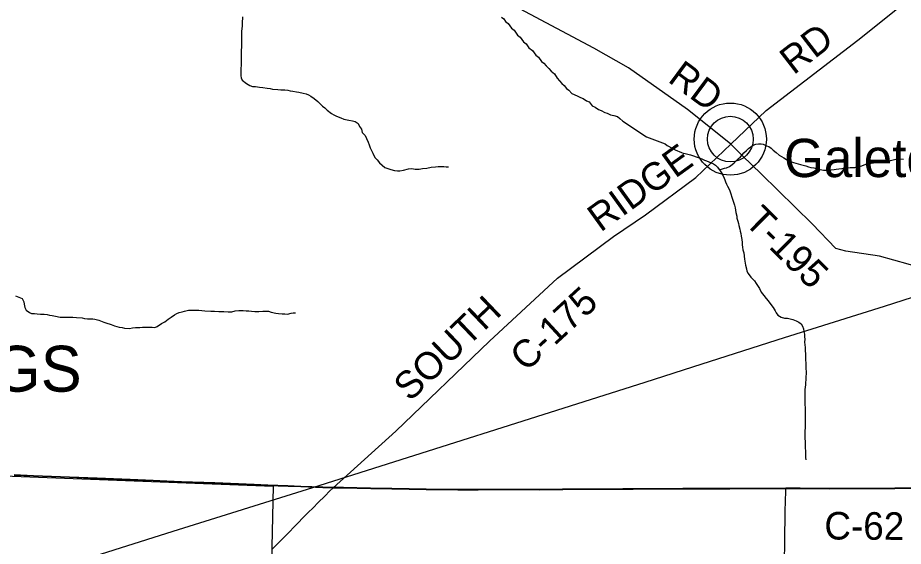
# Model space of a CAD drawing. Extents: x -8.5 to 18.7, y -20.3 to 7.
# Drawn here: x 4.267 to 7.92, y -11.043 to -8.863 of the extents above; entities that cross this region are included whole.
import ezdxf

# ---------------------------------------------------------------- set-up
doc = ezdxf.new("R2010")
doc.units = 0
for name, color, linetype in [('GM_X_Corporation', 7, 'Continuous'), ('GM_X_Corporation_Text', 7, 'Continuous'), ('GM_X_County_Road', 7, 'Continuous'), ('GM_X_County_Road_Text', 7, 'Continuous'), ('GM_X_Minor_River', 7, 'Continuous'), ('GM_X_Rail_Line', 7, 'Continuous'), ('GM_X_Section', 7, 'Continuous'), ('GM_X_Township', 7, 'Continuous'), ('GM_X_Township_Road', 7, 'Continuous'), ('GM_X_Township_Road_Text', 7, 'Continuous'), ('GM_X_Unincorporated', 7, 'Continuous'), ('GM_X_Unincorporated_Location', 7, 'Continuous'), ('GM_X_Unincorporated_Text', 7, 'Continuous'), ('SH_Cut_Line', 7, 'Continuous')]:
    doc.layers.add(name, color=color, linetype=linetype)

msp = doc.modelspace()

# ---------------------------------------------------------------- linework, layer by layer
at = {"layer": 'GM_X_Corporation'}
msp.add_lwpolyline([(8.0949, -10.8021), (7.8848, -10.8026), (7.748, -10.8038), (7.6138, -10.8041), (7.4944, -10.8032), (7.4521, -10.8028), (7.435, -10.8029), (7.2048, -10.8041), (7.1488, -10.8045), (7.0792, -10.8043), (7.0108, -10.8048), (6.9052, -10.8052), (6.8057, -10.806), (6.7635, -10.8059), (6.6528, -10.8065), (6.5148, -10.8074), (6.4203, -10.8081), (6.3109, -10.808), (6.1667, -10.8082), (6.0822, -10.8081), (5.9516, -10.8069), (5.882, -10.8055), (5.8099, -10.8045), (5.7229, -10.8027), (5.6109, -10.8007), (5.5922, -10.8003), (5.5684, -10.8), (5.5253, -10.7985), (5.4355, -10.7955), (5.3822, -10.7939), (5.2989, -10.7906), (5.243, -10.7881), (5.1784, -10.7854), (5.0803, -10.7812), (4.9424, -10.7762), (4.8828, -10.7737), (4.8257, -10.7709), (4.7313, -10.7671), (4.5946, -10.7618), (4.4816, -10.7572), (4.3325, -10.7515), (4.2528, -10.7486)], dxfattribs=at)
at = {"layer": 'GM_X_County_Road'}
for points in [[(5.5688, -10.8011), (5.8267, -10.5683), (6.2139, -10.1961), (6.4944, -9.937), (6.7242, -9.7652), (6.8562, -9.6754), (7.0642, -9.5212), (7.2089, -9.3842), (7.3538, -9.2453), (7.732, -8.955), (7.9241, -8.8029), (8.1243, -8.6374), (8.3921, -8.4103), (8.6752, -8.1728), (8.949, -7.9705)], [(4.2532, -10.7497), (4.3329, -10.7526), (4.482, -10.7583), (4.5951, -10.7629), (4.7317, -10.7682), (4.8261, -10.772), (4.8832, -10.7748), (4.9429, -10.7773), (5.0808, -10.7823), (5.1789, -10.7865), (5.2435, -10.7892), (5.2993, -10.7917), (5.3826, -10.795), (5.436, -10.7966), (5.5257, -10.7996), (5.5688, -10.8011)], [(5.5688, -10.8011), (5.5926, -10.8014), (5.6114, -10.8018), (5.7233, -10.8038), (5.8103, -10.8056), (5.8824, -10.8066), (5.952, -10.8081), (6.0826, -10.8092), (6.1672, -10.8093), (6.3114, -10.8091), (6.4208, -10.8092), (6.5153, -10.8085), (6.6533, -10.8076), (6.7639, -10.807), (6.8062, -10.8071), (6.9056, -10.8063), (7.0113, -10.806), (7.0797, -10.8054), (7.1493, -10.8056), (7.2052, -10.8052), (7.4354, -10.804)], [(7.4354, -10.804), (7.4526, -10.8039), (7.4948, -10.8043), (7.6142, -10.8052), (7.7485, -10.8049), (7.8853, -10.8037), (8.0954, -10.8032), (8.1911, -10.8034), (8.2757, -10.803), (8.3676, -10.8025), (8.4559, -10.8021), (8.5529, -10.8019), (8.6187, -10.8014), (8.697, -10.8019), (8.7703, -10.8018), (8.881, -10.802), (8.9257, -10.8016), (8.9531, -10.8017), (8.9971, -10.8024)]]:
    msp.add_lwpolyline(points, dxfattribs=at)
at = {"layer": 'GM_X_Minor_River'}
for points in [[(5.1941, -8.8584), (5.1938, -8.885), (5.1929, -8.8956), (5.1904, -8.9191), (5.1909, -8.9411), (5.1908, -8.9556), (5.1898, -8.973), (5.1904, -8.9852), (5.1895, -8.995), (5.1893, -9.0125), (5.1888, -9.0588), (5.1879, -9.0717), (5.1877, -9.0914), (5.1883, -9.1021), (5.1897, -9.1112), (5.1934, -9.1203), (5.2115, -9.1334), (5.225, -9.1427), (5.2364, -9.1459), (5.2477, -9.1467), (5.2644, -9.1492), (5.2781, -9.1501), (5.297, -9.1526), (5.3083, -9.155), (5.3182, -9.1566), (5.3409, -9.1591), (5.353, -9.16), (5.369, -9.1602), (5.3811, -9.1618), (5.3909, -9.1642), (5.4023, -9.1651), (5.4167, -9.1683), (5.4273, -9.1699), (5.4447, -9.1739), (5.4568, -9.1763), (5.4666, -9.181), (5.4764, -9.1856), (5.49, -9.1957), (5.505, -9.2087)], [(6.2623, -8.86), (6.272, -8.8677), (6.2788, -8.8784), (6.2908, -8.8861), (6.3035, -8.9052), (6.3148, -8.9145), (6.3282, -8.9343), (6.3402, -8.9421), (6.3529, -8.9619), (6.3642, -8.9704), (6.3761, -8.9872), (6.3904, -8.998)], [(6.3904, -8.998), (6.4039, -9.0164), (6.4152, -9.0249), (6.4279, -9.0425), (6.4369, -9.0494), (6.4474, -9.0617), (6.4586, -9.0716), (6.4676, -9.0831), (6.4819, -9.0939), (6.4931, -9.1115), (6.511, -9.1345), (6.5216, -9.1422), (6.5313, -9.1544), (6.5403, -9.1614), (6.5523, -9.1751), (6.5621, -9.1798), (6.5772, -9.186), (6.5885, -9.1915), (6.5991, -9.1961), (6.6134, -9.2054), (6.624, -9.2101), (6.6374, -9.2262), (6.6495, -9.2316), (6.663, -9.2416), (6.6736, -9.2455), (6.6887, -9.2541), (6.6993, -9.2564), (6.7129, -9.2627), (6.7257, -9.2658), (6.7408, -9.2706), (6.7506, -9.2782), (6.7626, -9.2898), (6.8613, -9.3538)], [(5.505, -9.2087), (5.5147, -9.2172), (5.5245, -9.2271), (5.5335, -9.2348), (5.544, -9.2441), (5.5621, -9.2572), (5.5719, -9.2626), (5.5824, -9.268), (5.5998, -9.2758), (5.6126, -9.2805), (5.6331, -9.2853), (5.6482, -9.2877), (5.6588, -9.2901), (5.6716, -9.2986), (5.6768, -9.3108), (5.6858, -9.3223), (5.6879, -9.336), (5.6999, -9.349), (5.7058, -9.3612), (5.7125, -9.3765), (5.7169, -9.3871), (5.7213, -9.3993), (5.7317, -9.4207), (5.7398, -9.439), (5.7496, -9.4482), (5.76, -9.4605), (5.7713, -9.4712), (5.7818, -9.4797), (5.806, -9.4891), (5.8219, -9.493), (5.834, -9.4947), (5.8431, -9.494), (5.8583, -9.4911), (5.8789, -9.486), (5.8933, -9.4847), (5.9069, -9.4871), (5.9228, -9.4873), (5.9373, -9.4844), (5.9548, -9.4831), (5.973, -9.4787), (5.9905, -9.4774), (6.0019, -9.476), (6.0246, -9.4762), (6.0345, -9.4771), (6.0436, -9.4772)], [(6.8613, -9.3538), (6.9378, -9.3833), (6.9455, -9.3901), (6.9698, -9.4014), (6.9797, -9.4074), (6.9881, -9.4119), (6.9957, -9.4149), (7.0048, -9.4187), (7.0124, -9.4209), (7.0208, -9.4232), (7.0421, -9.4284), (7.055, -9.4321), (7.0664, -9.4359), (7.074, -9.4389), (7.0816, -9.4419), (7.0915, -9.4456), (7.0999, -9.4501), (7.109, -9.4531), (7.1273, -9.4606), (7.1372, -9.4659), (7.1448, -9.4712), (7.1532, -9.4788), (7.1646, -9.4947), (7.173, -9.506), (7.1807, -9.5242), (7.1846, -9.5318), (7.1869, -9.5394), (7.1907, -9.5492), (7.1953, -9.5576), (7.203, -9.5727), (7.2061, -9.5811), (7.2091, -9.5887), (7.213, -9.6031), (7.2153, -9.6107), (7.2192, -9.6236), (7.2238, -9.6364), (7.2269, -9.6463), (7.2285, -9.6569), (7.23, -9.6653), (7.2331, -9.6812), (7.2339, -9.6888), (7.237, -9.7017), (7.2401, -9.7108), (7.2424, -9.7192), (7.2463, -9.7344), (7.2471, -9.7427), (7.2502, -9.7526), (7.2518, -9.7632), (7.2541, -9.7776), (7.255, -9.7898), (7.2558, -9.7996), (7.2566, -9.8088), (7.2589, -9.8201), (7.262, -9.833), (7.2652, -9.8589), (7.2683, -9.8756), (7.2698, -9.8832), (7.273, -9.8983), (7.2753, -9.9074), (7.2799, -9.9181), (7.2906, -9.9324), (7.2975, -9.94), (7.3059, -9.9483), (7.3127, -9.9582), (7.3189, -9.9665), (7.3273, -9.9794), (7.3342, -9.9945), (7.3449, -10.0089), (7.3548, -10.0203), (7.3625, -10.0301), (7.3732, -10.0452), (7.3831, -10.0574), (7.3915, -10.071), (7.3961, -10.0801), (7.4022, -10.0899), (7.4159, -10.0975), (7.4304, -10.1012), (7.4418, -10.1019), (7.4539, -10.1041), (7.4646, -10.1071), (7.4783, -10.1131), (7.4897, -10.1184), (7.4988, -10.1252), (7.5049, -10.135), (7.5088, -10.1464), (7.5104, -10.1563), (7.512, -10.1684), (7.5128, -10.1791), (7.5136, -10.1889), (7.5129, -10.2003), (7.5144, -10.2117), (7.5153, -10.2231), (7.5153, -10.2345), (7.5162, -10.2505), (7.517, -10.2596), (7.517, -10.2725), (7.5179, -10.2884), (7.5187, -10.3036), (7.5188, -10.3287), (7.5174, -10.3454), (7.5175, -10.3561)], [(7.1613, -9.49), (7.1828, -9.4832), (7.1904, -9.4816), (7.2033, -9.4762), (7.2146, -9.4678), (7.2222, -9.4617), (7.2312, -9.4533), (7.2388, -9.4449), (7.2486, -9.4358), (7.2562, -9.4274), (7.2629, -9.4197), (7.2728, -9.4098), (7.2818, -9.4014), (7.2909, -9.3945), (7.3015, -9.3884), (7.3121, -9.3838), (7.3227, -9.3822), (7.3341, -9.3822), (7.3425, -9.3844), (7.3554, -9.3912), (7.3661, -9.3942), (7.3752, -9.401), (7.3836, -9.4093), (7.3958, -9.4191), (7.408, -9.4297), (7.427, -9.441), (7.4377, -9.447), (7.4461, -9.4508), (7.459, -9.4568), (7.4674, -9.4598), (7.4765, -9.462), (7.4864, -9.465), (7.4955, -9.468), (7.5077, -9.471), (7.5183, -9.474), (7.529, -9.4777), (7.5388, -9.4799), (7.551, -9.4822), (7.5753, -9.4881), (7.5837, -9.4904), (7.5913, -9.4911), (7.611, -9.491), (7.6224, -9.4902), (7.6345, -9.4886), (7.6429, -9.487), (7.6543, -9.4855), (7.6672, -9.4839), (7.6778, -9.4823), (7.6884, -9.4815), (7.7005, -9.4807), (7.7119, -9.4806), (7.7203, -9.4798), (7.7279, -9.4775), (7.7385, -9.476), (7.7491, -9.4729), (7.7589, -9.469), (7.7703, -9.4652), (7.7779, -9.4636), (7.787, -9.462), (7.7969, -9.4605), (7.8075, -9.4589), (7.8234, -9.4581), (7.8318, -9.4573), (7.8393, -9.4572), (7.8522, -9.4557), (7.8598, -9.4541), (7.8674, -9.451), (7.878, -9.4487), (7.8894, -9.4464), (7.9, -9.4455), (7.9084, -9.4448), (7.9213, -9.4454)], [(4.2578, -10.0093), (4.2721, -10.0147), (4.2857, -10.0209), (4.2931, -10.0339), (4.2945, -10.0446), (4.2974, -10.0583), (4.3018, -10.0689), (4.3154, -10.079), (4.3245, -10.0821), (4.3366, -10.083), (4.3479, -10.0846), (4.3616, -10.0855), (4.376, -10.0857), (4.3889, -10.0873), (4.398, -10.0897), (4.4101, -10.0914), (4.4229, -10.0938), (4.4419, -10.097), (4.4942, -10.0976), (4.5094, -10.0993), (4.5336, -10.101), (4.5435, -10.1027), (4.5548, -10.1043)], [(4.5548, -10.1043), (4.5662, -10.1052), (4.5768, -10.1045), (4.5859, -10.1054), (4.6026, -10.1101), (4.6222, -10.1179), (4.6313, -10.1211), (4.6524, -10.1274), (4.666, -10.1328), (4.6759, -10.136), (4.6864, -10.1384), (4.6978, -10.1408), (4.7084, -10.1432), (4.7281, -10.1441), (4.741, -10.142), (4.7532, -10.1406), (4.7706, -10.14), (4.782, -10.1386), (4.8078, -10.1389), (4.8215, -10.139), (4.8328, -10.1399), (4.8428, -10.1362), (4.8611, -10.1243), (4.8748, -10.1168), (4.8886, -10.1064), (4.9001, -10.0974), (4.9138, -10.0884), (4.9238, -10.0824), (4.9329, -10.078), (4.9459, -10.0751), (4.9557, -10.0729), (4.9725, -10.0693), (4.993, -10.0688), (5.0043, -10.0689), (5.015, -10.069), (5.0271, -10.0699), (5.0392, -10.0715), (5.0635, -10.0733), (5.0794, -10.0727), (5.0976, -10.0744), (5.1181, -10.0747), (5.1355, -10.0756), (5.1507, -10.075), (5.1644, -10.0721), (5.1796, -10.07), (5.197, -10.0702), (5.2099, -10.0711), (5.2213, -10.072), (5.2319, -10.0736), (5.2448, -10.0737), (5.2622, -10.0739), (5.2789, -10.0733), (5.2918, -10.0727), (5.3017, -10.0736), (5.3123, -10.0767), (5.3327, -10.0815), (5.3433, -10.0831), (5.3577, -10.0841), (5.3691, -10.0842), (5.3804, -10.0851), (5.3949, -10.0814), (5.404, -10.08), (5.4131, -10.0793)], [(7.5175, -10.3561), (7.5168, -10.3675), (7.5168, -10.3781), (7.5153, -10.3857), (7.5146, -10.3979), (7.5139, -10.4062), (7.5142, -10.4602), (7.515, -10.4685), (7.5153, -10.5262), (7.5154, -10.549), (7.514, -10.5718), (7.5133, -10.5893), (7.5134, -10.5969), (7.5149, -10.6113), (7.5158, -10.6205), (7.516, -10.6668), (7.5168, -10.6759), (7.5176, -10.6858)]]:
    msp.add_lwpolyline(points, dxfattribs=at)
at = {"layer": 'GM_X_Rail_Line'}
for points in [[(5.485, -10.7997), (6.8557, -10.3656), (7.091, -10.2896), (7.4295, -10.182), (7.8426, -10.052), (7.9583, -10.0154)], [(4.5567, -11.0915), (4.9083, -10.98), (5.485, -10.7997)]]:
    msp.add_lwpolyline(points, dxfattribs=at)
at = {"layer": 'GM_X_Section'}
msp.add_lwpolyline([(3.3838, -10.7208), (5.3205, -10.7946), (5.2797, -12.6788), (3.2006, -12.6781), (3.25, -10.7172)], close=True, dxfattribs=at)
at = {"layer": 'GM_X_Township'}
msp.add_lwpolyline([(8.0949, -10.8021), (7.8848, -10.8026), (7.748, -10.8038), (7.6138, -10.8041), (7.4944, -10.8032), (7.4521, -10.8028), (7.435, -10.8029), (7.2048, -10.8041), (7.1488, -10.8045), (7.0792, -10.8043), (7.0108, -10.8048), (6.9052, -10.8052), (6.8057, -10.806), (6.7635, -10.8059), (6.6528, -10.8065), (6.5148, -10.8074), (6.4203, -10.8081), (6.3109, -10.808), (6.1667, -10.8082), (6.0822, -10.8081), (5.9516, -10.8069), (5.882, -10.8055), (5.8099, -10.8045), (5.7229, -10.8027), (5.6109, -10.8007), (5.5922, -10.8003), (5.5684, -10.8), (5.5253, -10.7985), (5.4355, -10.7955), (5.3822, -10.7939), (5.2989, -10.7906), (5.243, -10.7881), (5.1784, -10.7854), (5.0803, -10.7812), (4.9424, -10.7762), (4.8828, -10.7737), (4.8257, -10.7709), (4.7313, -10.7671), (4.5946, -10.7618), (4.4816, -10.7572), (4.3325, -10.7515), (4.2528, -10.7486)], dxfattribs=at)
at = {"layer": 'GM_X_Township_Road'}
for points in [[(7.1936, -9.3721), (7.0302, -9.2418), (6.787, -9.0687), (6.644, -8.9882), (6.3384, -8.826), (6.167, -8.7146), (5.5575, -7.9719)], [(9.1926, -10.7192), (9.0036, -10.6019), (8.7783, -10.4285), (8.4597, -10.1724), (8.178, -9.9487), (7.9407, -9.8786), (7.8216, -9.8466), (7.6826, -9.8258), (7.6424, -9.8138), (7.5441, -9.7128), (7.3344, -9.5061), (7.257, -9.432), (7.2089, -9.3842), (7.1936, -9.3721)], [(5.3184, -11.0539), (5.3256, -11.0462), (5.3716, -10.999), (5.4231, -10.9468), (5.4448, -10.9245), (5.4647, -10.9041), (5.4868, -10.8822), (5.5053, -10.8638), (5.5353, -10.8341), (5.5537, -10.816), (5.5688, -10.8011)], [(7.4237, -11.6555), (7.4244, -11.5579), (7.4257, -11.4758), (7.4268, -11.3788), (7.4284, -11.2917), (7.4292, -11.191), (7.4305, -11.1077), (7.4314, -11.0231), (7.4333, -10.8975), (7.4352, -10.8154), (7.4354, -10.804)]]:
    msp.add_lwpolyline(points, dxfattribs=at)
at = {"layer": 'GM_X_Unincorporated'}
for radius in [0.1488, 0.0943]:
    msp.add_circle((7.2066, -9.3632), radius, dxfattribs=at)
at = {"layer": 'GM_X_Unincorporated_Location'}
msp.add_line((7.2066, -9.3632), (7.2066, -9.3632), dxfattribs=at)
at = {"layer": 'SH_Cut_Line'}
for points in [[(8.0949, -10.8021), (7.8848, -10.8026), (7.748, -10.8038), (7.6138, -10.8041), (7.4944, -10.8032), (7.4521, -10.8028), (7.435, -10.8029), (7.2048, -10.8041), (7.1488, -10.8045), (7.0792, -10.8043), (7.0108, -10.8048), (6.9052, -10.8052), (6.8057, -10.806), (6.7635, -10.8059), (6.6528, -10.8065), (6.5148, -10.8074), (6.4203, -10.8081), (6.3109, -10.808), (6.1667, -10.8082), (6.0822, -10.8081), (5.9516, -10.8069), (5.882, -10.8055), (5.8099, -10.8045), (5.7229, -10.8027), (5.6109, -10.8007), (5.5922, -10.8003), (5.5684, -10.8), (5.5253, -10.7985), (5.4355, -10.7955), (5.3822, -10.7939), (5.2989, -10.7906), (5.243, -10.7881), (5.1784, -10.7854), (5.0803, -10.7812), (4.9424, -10.7762), (4.8828, -10.7737), (4.8257, -10.7709), (4.7313, -10.7671), (4.5946, -10.7618), (4.4816, -10.7572), (4.3325, -10.7515), (4.2528, -10.7486)], [(4.2528, -10.7486), (4.3325, -10.7515), (4.4816, -10.7572), (4.5946, -10.7618), (4.7313, -10.7671), (4.8257, -10.7709), (4.8828, -10.7737), (4.9424, -10.7762), (5.0803, -10.7812), (5.1784, -10.7854), (5.243, -10.7881), (5.2989, -10.7906), (5.3822, -10.7939), (5.4355, -10.7955), (5.5253, -10.7985), (5.5684, -10.8), (5.5922, -10.8003), (5.6109, -10.8007), (5.7229, -10.8027), (5.8099, -10.8045), (5.882, -10.8055), (5.9516, -10.8069), (6.0822, -10.8081), (6.1667, -10.8082), (6.3109, -10.808), (6.4203, -10.8081), (6.5148, -10.8074), (6.6528, -10.8065), (6.7635, -10.8059), (6.8057, -10.806), (6.9052, -10.8052), (7.0108, -10.8048), (7.0792, -10.8043), (7.1488, -10.8045), (7.2048, -10.8041), (7.435, -10.8029), (7.4521, -10.8028), (7.4944, -10.8032), (7.6138, -10.8041), (7.748, -10.8038), (7.8848, -10.8026), (8.0949, -10.8021)]]:
    msp.add_lwpolyline(points, dxfattribs=at)

# ---------------------------------------------------------------- texts
at = {"layer": 'GM_X_Corporation_Text'}
msp.add_text('GREEN SPRINGS', height=0.189394, rotation=0, dxfattribs=at).set_placement((2.4204, -10.405))
at = {"layer": 'GM_X_County_Road_Text'}
for s, rotation, p in [('RD', 37.6583, (7.4675, -9.101)), ('RIDGE', 35.8092, (6.6712, -9.7495)), ('C-175', 42.6625, (6.3636, -10.3266)), ('SOUTH', 43.6926, (5.8854, -10.4492)), ('C-62', 359.6632, (7.5942, -11.0145))]:
    msp.add_text(s, height=0.11364, rotation=rotation, dxfattribs=at).set_placement(p)
at = {"layer": 'GM_X_Township_Road_Text'}
for s, rotation, p in [('RD', 323.4237, (6.9444, -9.1236)), ('T-195', 315.1956, (7.2594, -9.7083))]:
    msp.add_text(s, height=0.11364, rotation=rotation, dxfattribs=at).set_placement(p)
at = {"layer": 'GM_X_Unincorporated_Text'}
msp.add_text('Galetown', height=0.15795, rotation=0, dxfattribs=at).set_placement((7.4281, -9.5199))

doc.saveas('drawing.dxf')
